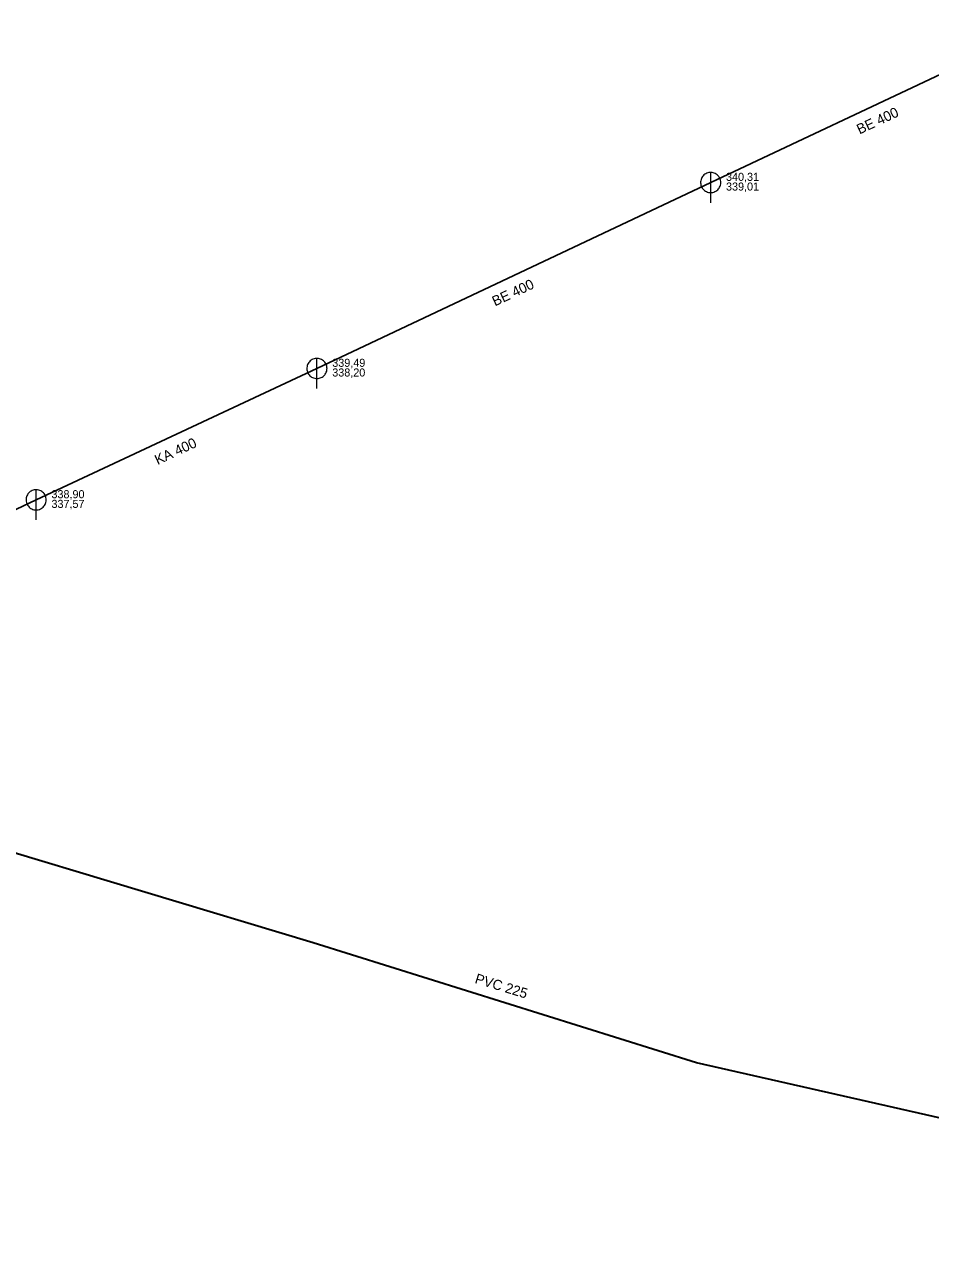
# Model space of a CAD drawing. Extents: x -724325 to -723665, y -972119 to -970722.
# Drawn here: x -724215.9 to -724126.1, y -971128.2 to -971006.2 of the extents above; entities that cross this region are included whole.
import ezdxf

# ---------------------------------------------------------------- set-up
doc = ezdxf.new("R2010")
doc.units = 0
doc.header["$LTSCALE"] = 0.4
for name, color, linetype, lineweight in [('1', 7, 'Continuous', 25), ('14', 7, 'Continuous', 25), ('17', 7, 'Continuous', 35), ('22', 7, 'Continuous', 13)]:
    doc.layers.add(name, color=color, linetype=linetype, lineweight=lineweight)
doc.layers.add('19', color=7, linetype='Continuous')

msp = doc.modelspace()

# ---------------------------------------------------------------- linework, layer by layer
at = {"layer": '14'}
for p, q in [((-724114.64, -971006.25), (-724147.899, -971021.91)), ((-724147.899, -971021.91), (-724186.94, -971040.35)), ((-724186.94, -971040.35), (-724214.78, -971053.379)), ((-724214.78, -971053.379), (-724230.75, -971060.969))]:
    msp.add_line(p, q, dxfattribs=at)
at = {"layer": '17'}
msp.add_lwpolyline([(-723856.75, -971277.52), (-723871.469, -971261.379), (-723894.09, -971234.91), (-723915.739, -971210.25), (-723934.449, -971190.379), (-723958.59, -971177.719), (-723983.8, -971165.17), (-724007.629, -971153.55), (-724038.03, -971139.35), (-724069.469, -971127.41), (-724098.62, -971120.079), (-724100.07, -971119.51), (-724120.89, -971115.66), (-724149.294, -971109.225), (-724187.32, -971097.32), (-724220.714, -971087.254), (-724255.679, -971055.409)], dxfattribs=at)
at = {"layer": '22'}
for p, q in [((-724147.899, -971023.91), (-724147.898, -971020.91)), ((-724186.94, -971042.35), (-724186.939, -971039.35)), ((-724214.78, -971055.379), (-724214.779, -971052.379))]:
    msp.add_line(p, q, dxfattribs=at)
for points in [[(-724146.899, -971021.91), (-724146.904, -971021.801), (-724146.922, -971021.693), (-724146.952, -971021.587), (-724146.992, -971021.486), (-724147.044, -971021.389), (-724147.106, -971021.299), (-724147.178, -971021.216), (-724147.258, -971021.142), (-724147.346, -971021.076), (-724147.44, -971021.021), (-724147.54, -971020.976), (-724147.645, -971020.943), (-724147.752, -971020.921), (-724147.861, -971020.911), (-724147.971, -971020.913), (-724148.079, -971020.927), (-724148.186, -971020.952), (-724148.289, -971020.989), (-724148.387, -971021.038), (-724148.479, -971021.096), (-724148.565, -971021.165), (-724148.642, -971021.242), (-724148.711, -971021.328), (-724148.77, -971021.42), (-724148.818, -971021.518), (-724148.855, -971021.621), (-724148.881, -971021.728), (-724148.895, -971021.836), (-724148.898, -971021.946), (-724148.888, -971022.055), (-724148.867, -971022.162), (-724148.833, -971022.266), (-724148.789, -971022.366), (-724148.734, -971022.461), (-724148.668, -971022.549), (-724148.594, -971022.629), (-724148.511, -971022.701), (-724148.421, -971022.763), (-724148.325, -971022.815), (-724148.223, -971022.856), (-724148.118, -971022.886), (-724148.01, -971022.904), (-724147.9, -971022.91), (-724147.791, -971022.904), (-724147.683, -971022.886), (-724147.578, -971022.857), (-724147.476, -971022.816), (-724147.379, -971022.764), (-724147.289, -971022.702), (-724147.206, -971022.631), (-724147.131, -971022.551), (-724147.066, -971022.463), (-724147.01, -971022.369), (-724146.966, -971022.269), (-724146.932, -971022.165), (-724146.91, -971022.057), (-724146.9, -971021.948)], [(-724185.94, -971040.35), (-724185.945, -971040.241), (-724185.963, -971040.133), (-724185.993, -971040.027), (-724186.033, -971039.926), (-724186.085, -971039.829), (-724186.147, -971039.739), (-724186.219, -971039.656), (-724186.299, -971039.582), (-724186.387, -971039.516), (-724186.481, -971039.461), (-724186.581, -971039.416), (-724186.686, -971039.383), (-724186.793, -971039.361), (-724186.902, -971039.351), (-724187.012, -971039.353), (-724187.12, -971039.367), (-724187.227, -971039.392), (-724187.33, -971039.429), (-724187.428, -971039.478), (-724187.52, -971039.536), (-724187.606, -971039.605), (-724187.683, -971039.682), (-724187.752, -971039.768), (-724187.811, -971039.86), (-724187.859, -971039.958), (-724187.896, -971040.061), (-724187.922, -971040.168), (-724187.936, -971040.276), (-724187.939, -971040.386), (-724187.929, -971040.495), (-724187.908, -971040.602), (-724187.874, -971040.706), (-724187.83, -971040.806), (-724187.775, -971040.901), (-724187.709, -971040.989), (-724187.635, -971041.069), (-724187.552, -971041.141), (-724187.462, -971041.203), (-724187.366, -971041.255), (-724187.264, -971041.296), (-724187.159, -971041.326), (-724187.051, -971041.344), (-724186.941, -971041.35), (-724186.832, -971041.344), (-724186.724, -971041.326), (-724186.619, -971041.297), (-724186.517, -971041.256), (-724186.42, -971041.204), (-724186.33, -971041.142), (-724186.247, -971041.071), (-724186.172, -971040.991), (-724186.107, -971040.903), (-724186.051, -971040.809), (-724186.007, -971040.709), (-724185.973, -971040.605), (-724185.951, -971040.497), (-724185.941, -971040.388)], [(-724213.78, -971053.379), (-724213.785, -971053.27), (-724213.803, -971053.162), (-724213.833, -971053.056), (-724213.873, -971052.955), (-724213.925, -971052.858), (-724213.987, -971052.768), (-724214.059, -971052.685), (-724214.139, -971052.611), (-724214.227, -971052.545), (-724214.321, -971052.49), (-724214.421, -971052.445), (-724214.526, -971052.412), (-724214.633, -971052.39), (-724214.742, -971052.38), (-724214.852, -971052.382), (-724214.96, -971052.396), (-724215.067, -971052.421), (-724215.17, -971052.458), (-724215.268, -971052.507), (-724215.36, -971052.565), (-724215.446, -971052.634), (-724215.523, -971052.711), (-724215.592, -971052.797), (-724215.651, -971052.889), (-724215.699, -971052.987), (-724215.736, -971053.09), (-724215.762, -971053.197), (-724215.776, -971053.305), (-724215.779, -971053.415), (-724215.769, -971053.524), (-724215.748, -971053.631), (-724215.714, -971053.735), (-724215.67, -971053.835), (-724215.615, -971053.93), (-724215.549, -971054.018), (-724215.475, -971054.098), (-724215.392, -971054.17), (-724215.302, -971054.232), (-724215.206, -971054.284), (-724215.104, -971054.325), (-724214.999, -971054.355), (-724214.891, -971054.373), (-724214.781, -971054.379), (-724214.672, -971054.373), (-724214.564, -971054.355), (-724214.459, -971054.326), (-724214.357, -971054.285), (-724214.26, -971054.233), (-724214.17, -971054.171), (-724214.087, -971054.1), (-724214.012, -971054.02), (-724213.947, -971053.932), (-724213.891, -971053.838), (-724213.847, -971053.738), (-724213.813, -971053.634), (-724213.791, -971053.526), (-724213.781, -971053.417)]]:
    msp.add_lwpolyline(points, close=True, dxfattribs=at)

# ---------------------------------------------------------------- texts
at = {"layer": '1'}
for s, rotation, p in [('BE 400', 25, (-724133.138, -971017.153)), ('BE 400', 25, (-724169.284, -971034.205)), ('KA 400', 25, (-724202.735, -971049.934)), ('PVC 225 ', 343, (-724171.352, -971101.286))]:
    msp.add_text(s, height=1, rotation=rotation, dxfattribs=at).set_placement(p)
at = {"layer": '19'}
for s, p in [('340,31', (-724146.378, -971021.75)), ('339,01', (-724146.378, -971022.71)), ('339,49', (-724185.418, -971040.189)), ('338,20', (-724185.418, -971041.149)), ('338,90', (-724213.258, -971053.22)), ('337,57', (-724213.258, -971054.18))]:
    msp.add_text(s, height=0.8, dxfattribs=at).set_placement(p)

doc.saveas('drawing.dxf')
